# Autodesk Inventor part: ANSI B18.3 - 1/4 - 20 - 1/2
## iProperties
Comments: To add or edit properties for Autodesk Inventor files, use iProperties.
Created: 2004-06
Part Number: ANSI B18.3 - 1/4 - 20 - 1/2
Vendor: Autodesk Inc.
Document SubType Name: Modeling
Designer: jpittman
Material: Default
Description: Hexagon Socket Head Cap Screw
Standard: ANSI B18.3
Alert: To add or edit properties for Autodesk Inventor files, use iProperties.
Control State: 0
Master: False
Checked Out: False
Shininess: 64.0
Length Units: 11272
Angle Units: 11279
Time Units: 11290
Mass Units: 11286
Length Display Precision: 3
Angle Display Precision: 2
Compacted: True
EGR: 3
Classification: un/spsc 31161501
Density: 0.0
Volumn: 0.0
Area: 0.0
PropertySet Name: Model Information
Author: jpittman
Revision Number: 8
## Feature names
1. Body [Revolution]
2. Slot [Extrusion]
3. Fillet1
4. Chamfer1
